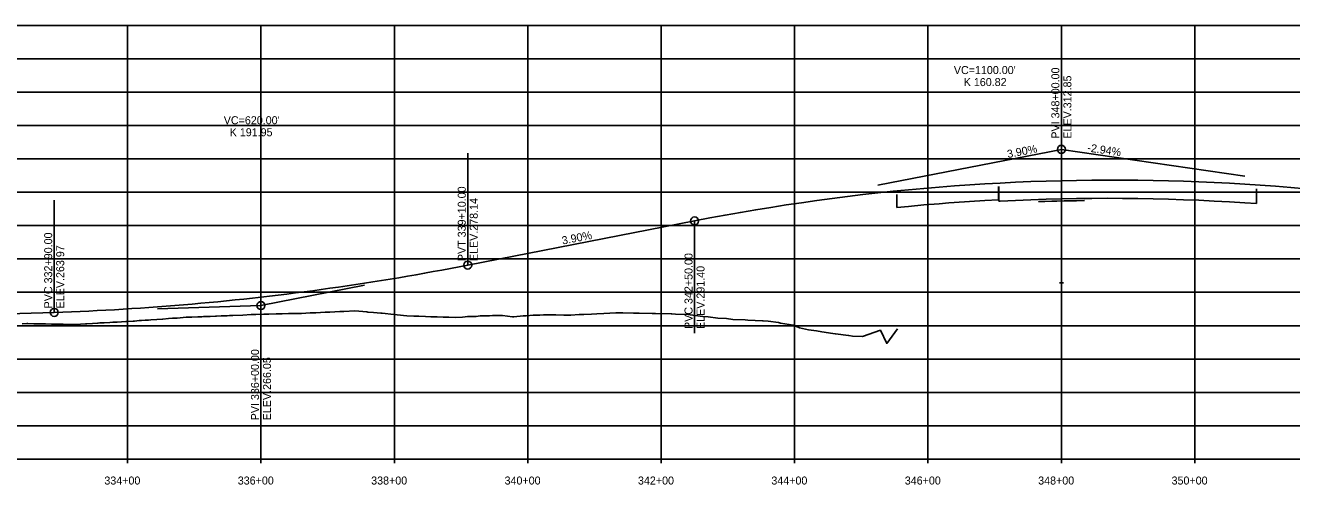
# Model space of a CAD drawing. Extents: x 880555 to 887700, y 1561392 to 1563161.
# Drawn here: x 882477 to 884376, y 1562454 to 1563143 of the extents above; entities that cross this region are included whole.
import ezdxf

# ---------------------------------------------------------------- set-up
doc = ezdxf.new("R2010")
doc.units = 0
for name, color, linetype in [('1', 7, 'Continuous'), ('30', 7, 'Continuous'), ('37', 7, 'Continuous'), ('56', 7, 'Continuous'), ('B_Steel', 7, 'Continuous'), ('Default', 7, 'Continuous'), ('R_Exist Surface', 7, 'Continuous')]:
    doc.layers.add(name, color=color, linetype=linetype)

msp = doc.modelspace()

# ---------------------------------------------------------------- linework, layer by layer
at = {"layer": '1'}
for p, q in [((883755.6, 1562903.2), (884030.6, 1562956.8)), ((884030.6, 1562956.8), (884305.6, 1562916.4)), ((882830.6, 1562722.8), (882985.6, 1562753.1)), ((882675.6, 1562717.6), (882830.6, 1562722.8))]:
    msp.add_line(p, q, dxfattribs=at)
at = {"layer": '37'}
for p, q in [((880630.6, 1563142.6), (887630.6, 1563142.6)), ((880630.6, 1563142.6), (887630.6, 1563142.6)), ((882630.6, 1562492.6), (882630.6, 1563142.6)), ((882830.6, 1562492.6), (882830.6, 1563142.6)), ((883030.6, 1562492.6), (883030.6, 1563142.6)), ((883230.6, 1562492.6), (883230.6, 1563142.6)), ((883430.6, 1562492.6), (883430.6, 1563142.6)), ((883630.6, 1562492.6), (883630.6, 1563142.6)), ((883830.6, 1562492.6), (883830.6, 1563142.6)), ((884030.6, 1562492.6), (884030.6, 1563142.6)), ((884230.6, 1562492.6), (884230.6, 1563142.6)), ((880630.6, 1563092.6), (887630.6, 1563092.6)), ((880630.6, 1563042.6), (887630.6, 1563042.6)), ((880630.6, 1562992.6), (887630.6, 1562992.6)), ((880630.6, 1562942.6), (887630.6, 1562942.6)), ((880630.6, 1562892.6), (887630.6, 1562892.6)), ((880630.6, 1562842.6), (887630.6, 1562842.6)), ((880630.6, 1562792.6), (887630.6, 1562792.6)), ((880630.6, 1562742.6), (887630.6, 1562742.6)), ((880630.6, 1562692.6), (887630.6, 1562692.6)), ((880630.6, 1562642.6), (887630.6, 1562642.6)), ((880630.6, 1562592.6), (887630.6, 1562592.6)), ((880630.6, 1562542.6), (887630.6, 1562542.6)), ((880630.6, 1562492.6), (887630.6, 1562492.6)), ((882630.6, 1562486.6), (882630.6, 1562492.6)), ((882830.6, 1562486.6), (882830.6, 1562492.6)), ((883030.6, 1562486.6), (883030.6, 1562492.6)), ((883230.6, 1562486.6), (883230.6, 1562492.6)), ((883430.6, 1562486.6), (883430.6, 1562492.6)), ((883630.6, 1562486.6), (883630.6, 1562492.6)), ((883830.6, 1562486.6), (883830.6, 1562492.6)), ((884030.6, 1562486.6), (884030.6, 1562492.6)), ((884230.6, 1562486.6), (884230.6, 1562492.6))]:
    msp.add_line(p, q, dxfattribs=at)
at = {"layer": '56'}
for p, q in [((884030.6, 1562966.8), (884030.6, 1563134.8)), ((884030.6, 1562956.8), (884030.6, 1562966.8)), ((883140.6, 1562783.3), (883140.6, 1562951.3)), ((882520.6, 1562712.5), (882520.6, 1562880.5)), ((883140.6, 1562783.3), (883480.6, 1562849.6)), ((883480.6, 1562849.6), (883480.6, 1562681.6)), ((882830.6, 1562722.8), (882830.6, 1562712.8)), ((881730.6, 1562686), (882520.6, 1562712.5)), ((882830.6, 1562712.8), (882830.6, 1562544.8))]:
    msp.add_line(p, q, dxfattribs=at)
for points in [[(883480.6, 1562849.6), (883503.5, 1562854), (883526.4, 1562858.2), (883549.4, 1562862.3), (883572.3, 1562866.2), (883595.2, 1562869.9), (883618.1, 1562873.5), (883641, 1562876.9), (883663.9, 1562880.1), (883686.9, 1562883.2), (883709.8, 1562886.1), (883732.7, 1562888.9), (883755.6, 1562891.5), (883778.5, 1562893.9), (883801.4, 1562896.2), (883824.4, 1562898.3), (883847.3, 1562900.2), (883870.2, 1562902), (883893.1, 1562903.6), (883916, 1562905), (883938.9, 1562906.3), (883961.9, 1562907.4), (883984.8, 1562908.4), (884007.7, 1562909.2), (884053.5, 1562910.3), (884076.4, 1562910.6), (884099.4, 1562910.7), (884122.3, 1562910.7), (884145.2, 1562910.5), (884168.1, 1562910.2), (884191, 1562909.7), (884213.9, 1562909), (884236.9, 1562908.2), (884259.8, 1562907.2), (884282.7, 1562906), (884305.6, 1562904.7), (884328.5, 1562903.2), (884351.4, 1562901.5), (884374.4, 1562899.7), (884397.3, 1562897.7)], [(882520.6, 1562712.5), (882533.5, 1562712.9), (882546.4, 1562713.4), (882559.4, 1562713.9), (882572.3, 1562714.5), (882585.2, 1562715.2), (882598.1, 1562715.8), (882611, 1562716.5), (882623.9, 1562717.3), (882636.9, 1562718.1), (882649.8, 1562719), (882662.7, 1562719.8), (882675.6, 1562720.8), (882688.5, 1562721.8), (882701.4, 1562722.8), (882714.4, 1562723.8), (882727.3, 1562724.9), (882740.2, 1562726.1), (882753.1, 1562727.3), (882766, 1562728.5), (882778.9, 1562729.8), (882791.9, 1562731.1), (882804.8, 1562732.5), (882817.7, 1562733.9), (882843.5, 1562736.9), (882856.4, 1562738.4), (882869.4, 1562740), (882882.3, 1562741.6), (882895.2, 1562743.3), (882908.1, 1562745), (882921, 1562746.8), (882933.9, 1562748.6), (882946.9, 1562750.4), (882959.8, 1562752.3), (882972.7, 1562754.2), (882985.6, 1562756.2), (882998.5, 1562758.2), (883011.4, 1562760.3), (883024.4, 1562762.4), (883037.3, 1562764.5), (883050.2, 1562766.7), (883063.1, 1562769), (883076, 1562771.2), (883088.9, 1562773.6), (883101.9, 1562775.9), (883114.8, 1562778.3), (883127.7, 1562780.8), (883140.6, 1562783.3)]]:
    msp.add_lwpolyline(points, dxfattribs=at)
for centre in [(884030.6, 1562956.8), (883480.6, 1562849.6), (883140.6, 1562783.3), (882520.6, 1562712.5), (882830.6, 1562722.8)]:
    msp.add_circle(centre, 6, dxfattribs=at)
at = {"layer": 'B_Steel'}
for p, q in [((883784.1, 1562889.2), (883784.1, 1562869.6)), ((883936.5, 1562901.1), (883936.5, 1562881.4)), ((883936.7, 1562879.2), (883936.7, 1562901.1)), ((884322.9, 1562897.4), (884322.9, 1562875.5))]:
    msp.add_line(p, q, dxfattribs=at)
for points in [[(883784.1, 1562869.6), (883801.4, 1562871.3), (883824.4, 1562873.5), (883847.3, 1562875.4), (883861.9, 1562876.6)], [(883861.9, 1562876.6), (883870, 1562877.2), (883892.9, 1562878.8), (883915.8, 1562880.3), (883936.5, 1562881.4)], [(883936.7, 1562879.2), (883938.9, 1562879.3), (883961.9, 1562880.4), (883984.8, 1562881.4), (884007.7, 1562882.1), (884053.5, 1562883.2), (884076.4, 1562883.4), (884099.4, 1562883.5), (884122.3, 1562883.4), (884145.2, 1562883.2), (884168.1, 1562882.8), (884191, 1562882.2), (884213.9, 1562881.4), (884236.9, 1562880.5), (884259.8, 1562879.4), (884282.7, 1562878.1), (884305.6, 1562876.7), (884322.9, 1562875.5)]]:
    msp.add_lwpolyline(points, dxfattribs=at)
at = {"layer": 'Default'}
for points in [[(883996.1, 1562878.4), (883997.7, 1562878.5), (883998.1, 1562878.5), (884003.5, 1562878.6), (884004.2, 1562878.6), (884006, 1562878.7), (884016.4, 1562879), (884023.8, 1562879.2), (884034.8, 1562879.5), (884048.8, 1562879.8), (884053.2, 1562879.9), (884065.2, 1562880.3)], [(884027.7, 1562756.8), (884029.9, 1562756.8), (884030.7, 1562756.8), (884033.4, 1562756.9), (884033.6, 1562756.9)]]:
    msp.add_lwpolyline(points, dxfattribs=at)
at = {"layer": 'R_Exist Surface'}
msp.add_lwpolyline([(882472.4, 1562695.5), (882479.4, 1562695.7), (882481.2, 1562695.7), (882490, 1562695.5), (882498.4, 1562695.3), (882498.8, 1562695.3), (882503, 1562695.4), (882507.5, 1562695.3), (882516.3, 1562695.1), (882524.8, 1562694.9), (882525.1, 1562694.9), (882526.5, 1562694.9), (882533.9, 1562694.7), (882540, 1562694.5), (882542.7, 1562694.4), (882550.1, 1562694.2), (882551.4, 1562694.3), (882560.2, 1562694.9), (882567.5, 1562695.5), (882569, 1562695.5), (882569.6, 1562695.5), (882577.8, 1562696.1), (882585.6, 1562696.6), (882586.6, 1562696.6), (882589.2, 1562696.7), (882593.6, 1562696.9), (882595.3, 1562697), (882604.1, 1562697.6), (882608.6, 1562697.8), (882612.9, 1562698), (882615, 1562698), (882621.7, 1562698.4), (882628.1, 1562698.8), (882630.5, 1562699), (882639.2, 1562699.5), (882640.9, 1562699.6), (882648, 1562700.2), (882651.3, 1562700.4), (882656.8, 1562700.8), (882662.2, 1562701.1), (882665.6, 1562701.4), (882674.4, 1562702), (882674.6, 1562702), (882683.1, 1562702.6), (882683.5, 1562702.6), (882691.9, 1562703.3), (882698, 1562703.7), (882700.7, 1562703.9), (882704.7, 1562704.1), (882709.5, 1562704.5), (882718.3, 1562705.2), (882721.4, 1562705.4), (882727, 1562705.6), (882735.8, 1562705.9), (882740, 1562706), (882742, 1562706.1), (882744.6, 1562706.2), (882753.4, 1562706.4), (882754.5, 1562706.5), (882762.2, 1562706.8), (882762.6, 1562706.8), (882763.9, 1562706.9), (882770.9, 1562707.2), (882779.7, 1562707.6), (882783.2, 1562707.7), (882787.6, 1562707.9), (882788.5, 1562707.9), (882803.6, 1562708.6), (882816.1, 1562709.2), (882823.1, 1562709.3), (882834.7, 1562709.9), (882842.6, 1562709.9), (882853.2, 1562710.5), (882862.2, 1562710.5), (882871.7, 1562710.9), (882881.7, 1562710.9), (882891.4, 1562711.1), (882904.2, 1562711.8), (882912.6, 1562711.9), (882926.7, 1562712.7), (882933.8, 1562712.8), (882949, 1562713.7), (882955, 1562713.8), (882971.4, 1562714.8), (882989.2, 1562713.3), (882990.9, 1562713.1), (882999.5, 1562712.4), (883010.3, 1562711.5), (883012.2, 1562711.2), (883029.7, 1562709.5), (883034.9, 1562708.7), (883049.1, 1562707.3), (883059.8, 1562706.8), (883067.3, 1562706.7), (883077.2, 1562706.2), (883085.4, 1562706.1), (883094.7, 1562705.7), (883103.6, 1562705.6), (883112.2, 1562705.2), (883121.9, 1562705.1), (883132.7, 1562705.2), (883140.6, 1562706.6), (883153, 1562706.6), (883159.3, 1562707.5), (883173.1, 1562707.4), (883177.8, 1562708.1), (883192.9, 1562707.8), (883207.7, 1562706), (883208.2, 1562706.1), (883209.9, 1562705.8), (883223.5, 1562707.3), (883228.1, 1562707.4), (883238.9, 1562708.4), (883248.5, 1562708.5), (883254.3, 1562708.9), (883268.6, 1562708.8), (883269.6, 1562708.8), (883272.7, 1562708.7), (883284.8, 1562708.5), (883295.2, 1562708.3), (883307.7, 1562709.2), (883314.7, 1562709.4), (883326.1, 1562710.1), (883334.2, 1562710.3), (883344.4, 1562710.9), (883353.7, 1562711.2), (883362.8, 1562711.7), (883373.1, 1562711.9), (883388.9, 1562711.6), (883397.7, 1562711.6), (883417.2, 1562711), (883422.2, 1562711), (883445.6, 1562710.3), (883446.6, 1562710.3), (883452.3, 1562710.1), (883470.9, 1562709.3), (883473.9, 1562709), (883493.2, 1562706.4), (883500.9, 1562705.8), (883515.6, 1562704), (883528.4, 1562703.2), (883538.1, 1562702.1), (883556.3, 1562701.2), (883560.7, 1562700.7), (883582.5, 1562699.7), (883583.5, 1562699.7), (883591.1, 1562699.3), (883606.3, 1562697.6), (883609.3, 1562696.5), (883629, 1562693.5), (883637.8, 1562689.5), (883651.4, 1562686.6), (883663.6, 1562684.8), (883671.6, 1562683.3), (883687.9, 1562681), (883691.8, 1562680.3), (883711.3, 1562677.8), (883712, 1562677.7), (883717.3, 1562677), (883732.3, 1562676.6), (883759.3, 1562685.7), (883768.9, 1562666), (883784.8, 1562688.1)], dxfattribs=at)

# ---------------------------------------------------------------- texts
at = {"layer": '30'}
for s, p in [('334+00', (882595.8, 1562454.6)), ('336+00', (882795.8, 1562454.6)), ('338+00', (882995.8, 1562454.6)), ('340+00', (883195.8, 1562454.6)), ('342+00', (883395.8, 1562454.6)), ('344+00', (883595.8, 1562454.6)), ('346+00', (883795.8, 1562454.6)), ('348+00', (883995.8, 1562454.6)), ('350+00', (884195.8, 1562454.6))]:
    msp.add_text(s, height=12, dxfattribs=at).set_placement(p)
at = {"layer": '56'}
for s, p in [("VC=1100.00'", (883869.4, 1563069.6)), ('K 160.82', (883884.2, 1563051.6)), ("VC=620.00'", (882774.8, 1562994.4)), ('K 191.95', (882783.7, 1562976.4))]:
    msp.add_text(s, height=12, dxfattribs=at).set_placement(p)
for s, rotation, p in [('PVI 348+00.00', 90, (884027.6, 1562972.8)), ('ELEV.312.85', 90, (884045.6, 1562972.8)), ('3.90%', 11.0342, (883950.4, 1562943.6)), ('-2.94%', 351.6374, (884068.9, 1562953.7)), ('PVT 339+10.00', 90, (883137.6, 1562789.3)), ('ELEV.278.14', 90, (883155.6, 1562789.3)), ('3.90%', 11.0342, (883283, 1562814.1)), ('PVC 332+90.00', 90, (882517.6, 1562718.5)), ('ELEV.263.97', 90, (882535.6, 1562718.5)), ('PVC 342+50.00', 90, (883477.6, 1562687.6)), ('ELEV.291.40', 90, (883495.6, 1562687.6)), ('PVI 336+00.00', 90, (882827.6, 1562550.8)), ('ELEV.266.05', 90, (882845.6, 1562550.8))]:
    msp.add_text(s, height=12, rotation=rotation, dxfattribs=at).set_placement(p)

doc.saveas('drawing.dxf')
